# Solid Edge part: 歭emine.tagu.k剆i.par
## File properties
Author: Türk
Template: Iso Part.par
Last saved by: Türk
Revision: 3
Application: Solid Edge
Accuracy: 0,990
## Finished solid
Body 1: solid body, 46 faces, 101 edges, 54 vertices.
  Faces by surface: cylinder 18, plane 12, torus 12, blend 4
  Edges by curve: circle 40, intersection 32, line 22, ellipse 7
Bounding box of the edges (mm; curved faces can reach further): 300.000 x 118.000 x 100.000, from (-275, 0, -25) to (25, 118, 75).
Cylindrical faces by radius (mm): R5 x2, R10.5 x4, R15 x8, R25 x4
Toroidal faces (ring radius, tube radius in mm): R11 r0.5 x4, R24.5 r0.5 x4, R382.2518 r3 x2, R400 r15 x2
Planar faces by outward normal: +x 1, +y 4, +z 1, -x 1, -y 4, -z 1
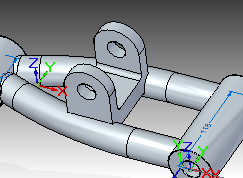
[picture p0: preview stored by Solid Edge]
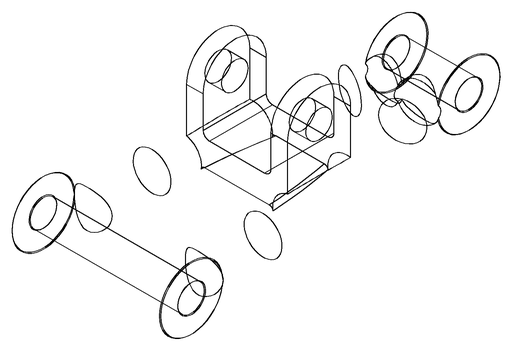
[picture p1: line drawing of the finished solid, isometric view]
